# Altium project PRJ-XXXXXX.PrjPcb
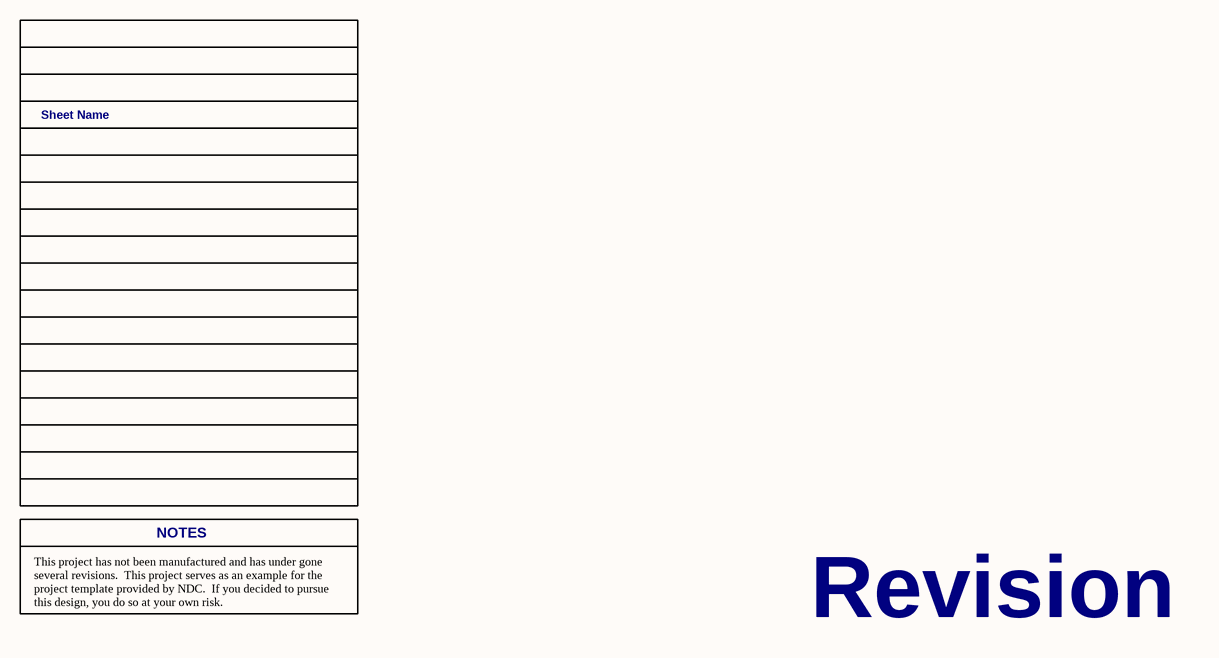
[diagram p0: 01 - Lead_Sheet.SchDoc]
BlockAddrLine1: [BlockAddrLine1]; BlockAddrLine2: [BlockAddrLine2]; BlockAddrLine3: [BlockAddrLine3]; BlockCAGEcode: [00XX0]; BlockCompanyName: [BlockCompanyName]; BlockCompanyWebsite: [website address]; BlockDocNumber: [Doc Number]; BlockNameDesigner: [Name of Designer]; BlockNamePM: [Name of PM]; BlockNameReviewer: [Name of Reviewer]; BlockProjectName: [Doc Name]; BlockRev: [Rev]; BlockSheetSize: [SIZE]; BlockStartDate: [mm-dd-yyyy]; DrftmnPNAsy: [Draftsman Asy #]; DrftmnPNFab: [Draftsman Fab #]; DrftmnTitleAsy: Assembly Drawing; DrftmnTitleFab: Fabrication Drawing; SchSheetName1: 01 - Lead Sheet; SchSheetName2: 02 - System Block Diagram; SchSheetName3: 03 - Power Delivery; SchSheetName4: 04 -
5 sheets, 12 parts. Net scope: global (net labels, ports and power ports of the same name join across sheets).
Board file: PWB-XXXXXX.PcbDoc
Sheets:
  01 - Lead_Sheet.SchDoc
  02 - Block_Diagram.SchDoc
  03 - .SchDoc
  04 - .SchDoc
  XX - Back Page.SchDoc

## Sheet 01 - Lead_Sheet.SchDoc
size B; DocumentNumber: 1; SheetNumber: 1; SheetTotal: 10; PageSetup: Record=PageOptions¦CenterHorizontal=True¦CenterVertical=True¦PrintScale=0.72¦XCorrection=1.00¦YCorrection=1.00¦PrintKind=1¦BorderSize=5000000¦LeftOffset=0¦BottomOffset=0¦Orientation=2¦PaperLength=1000¦PaperWidth=1000¦Scale=100¦PaperSource=15¦PrintQuality=4000¦MediaType=1¦DitherType=10¦PaperKind=Letter¦PrintScaleMode=1

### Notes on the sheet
- Sheet Name
- NOTES
- This project has not been manufactured and has under gone several revisions.  This project serves as an example for the project template provided by NDC.  If you decided to pursue this design, you do so at your own risk.
- Revision

## Sheet 02 - Block_Diagram.SchDoc
size B; DocumentNumber: 2; SheetNumber: 2; SheetTotal: 10
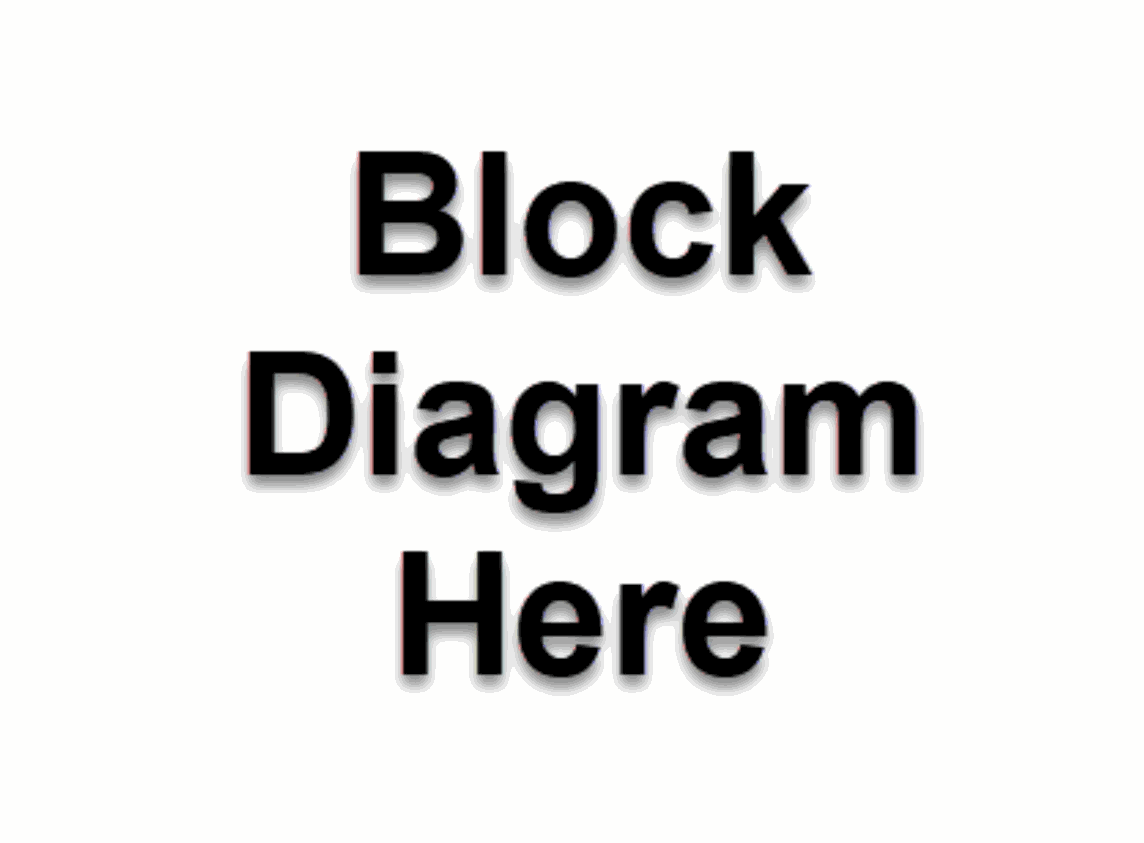
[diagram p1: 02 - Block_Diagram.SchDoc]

## Sheet 03 - .SchDoc
size B; DocumentNumber: 3; SheetNumber: 3; SheetTotal: 10

## Sheet 04 - .SchDoc
size B; DocumentNumber: 4; SheetNumber: 4; SheetTotal: 10

## Sheet XX - Back Page.SchDoc
size B; DocumentNumber: 10; SheetNumber: 10; SheetTotal: 10
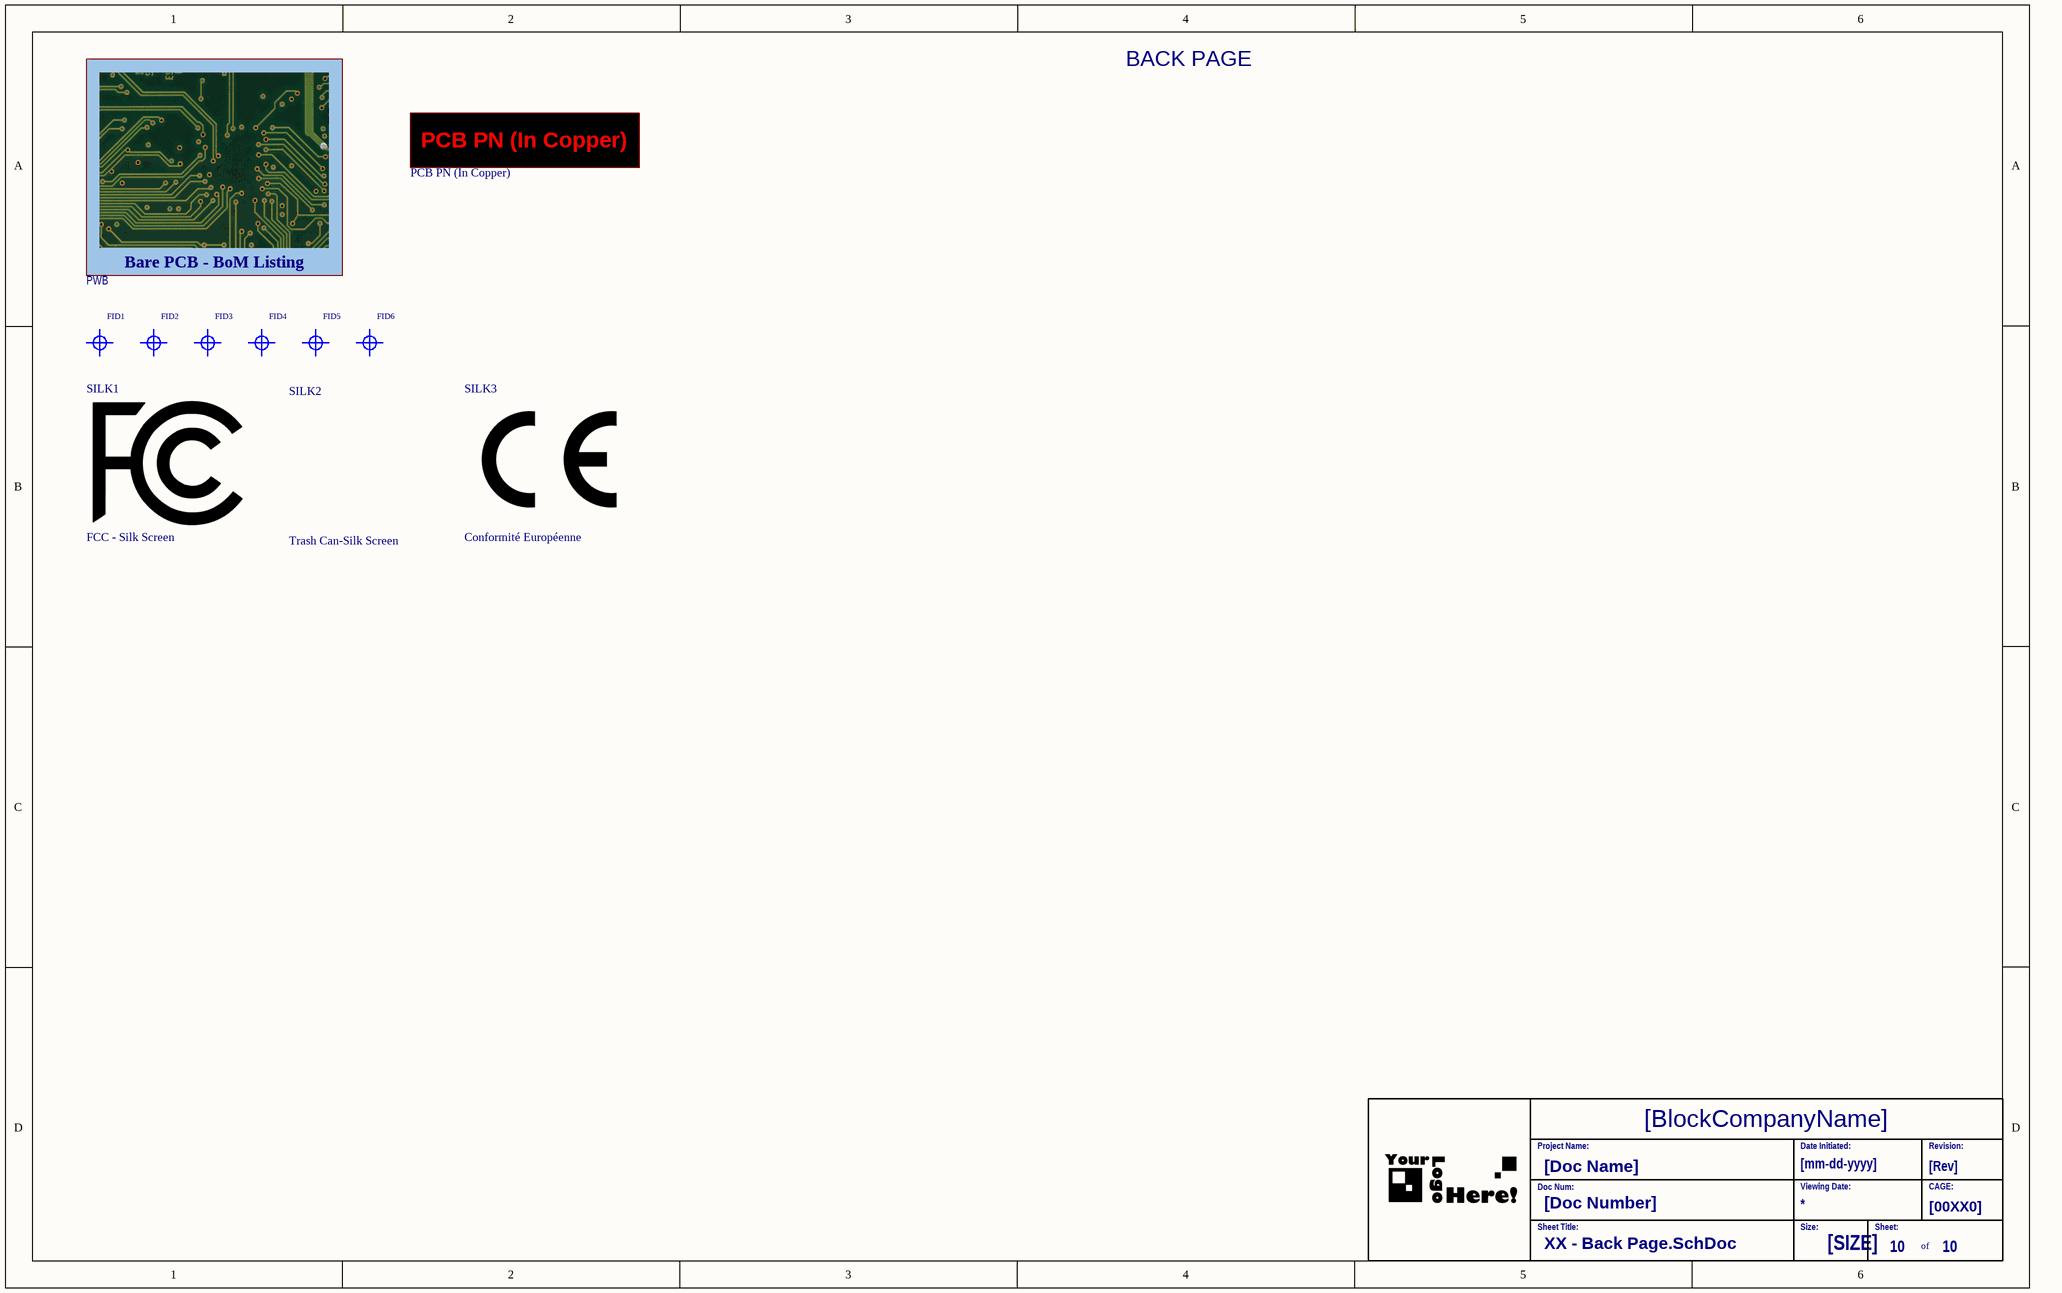
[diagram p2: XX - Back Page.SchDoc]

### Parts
FAB1  PWB  (mechanical)
FID1  Fiducial, 1:3mm  [FIDUCIAL 1MM]  (value not drawn)  (no BOM)
FID2  Fiducial, 1:3mm  [FIDUCIAL 1MM]  (value not drawn)  (no BOM)
FID3  Fiducial, 1:3mm  [FIDUCIAL 1MM]  (value not drawn)  (no BOM)
FID4  Fiducial, 1:3mm  [FIDUCIAL 1MM]  (value not drawn)  (no BOM)
FID5  Fiducial, 1:3mm  [FIDUCIAL 1MM]  (value not drawn)  (no BOM)
FID6  Fiducial, 1:3mm  [FIDUCIAL 1MM]  (value not drawn)  (no BOM)
PCB_PN_(In_Copper)1  PCB PN (In Copper)  [PCB PN (In Copper)]  (no BOM)
SILK1  FCC - Silk Screen  [LOGO - FCC]  (no BOM)
SILK2  Trash Can-Silk Screen  [LOGO - NO THROW]  (no BOM)
SILK3  Conformité Européenne  [Logo - European Conformity]  (no BOM)
TitleBlockxx  Title Block - Abbreviated  (value not drawn)  (graphical)

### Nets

Not connected (* = marked no-connect by the designer): FID1 1(NC); FID2 1(NC); FID3 1(NC); FID4 1(NC); FID5 1(NC); FID6 1(NC)

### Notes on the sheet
- BACK PAGE

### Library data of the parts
FAB1 = BOM - Bare PCB PN: Bare PCB Part Number
FID1-FID6 = PCB - Fiducial
PCB_PN_(In_Copper)1 = PCB - PN in CU: PCB Part Number (In Copper)
SILK1 = Silk Screen - FCC
SILK2 = Silk Screen - No Throw Out
SILK3 = Silkscreen - European Conformity
TitleBlockxx = Title Block - Abbreviated: Title Block for company.  Textual information is either linked to the parameters listed in the project options or "as is" text

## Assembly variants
Proto: all parts fitted
Production: all parts fitted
